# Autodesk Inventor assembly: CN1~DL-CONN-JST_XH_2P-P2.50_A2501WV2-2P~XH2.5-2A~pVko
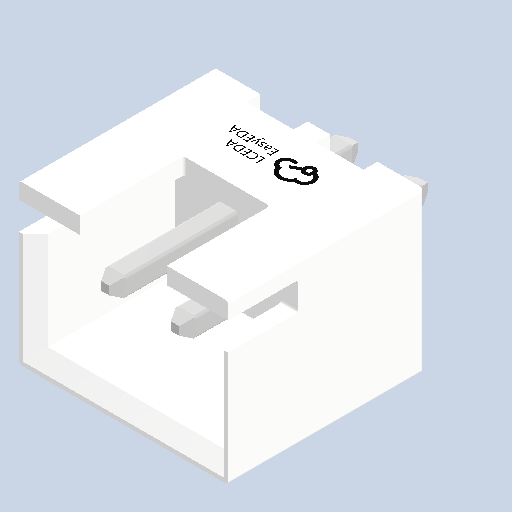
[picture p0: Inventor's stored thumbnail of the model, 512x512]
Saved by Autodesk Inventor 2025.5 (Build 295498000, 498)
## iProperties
Created: 2026-10
Part Number: CN1~DL-CONN-JST_XH_2P-P2.50_A2501WV2-2P~XH2.5-2A~pVko
Document SubType Name: Assembly
Designer: Luis M
Author: Luis M
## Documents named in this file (2)
- C:\Users\Luis M\Downloads\3D_PCB1_2026-10-28\CN1~DL-CONN-JST_XH_2P-P2.50_A2501WV2-2P~XH2.5-2A~pVko.iam
- C:\Users\Luis M\Downloads\3D_PCB1_2026-10-28\DL-CONN-JST_XH_2P-P2.50_A2501WV2-2P~XH2.5-2A~i7Qw.ipt
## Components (1 placed, 1 different names)
1. CN1->0
